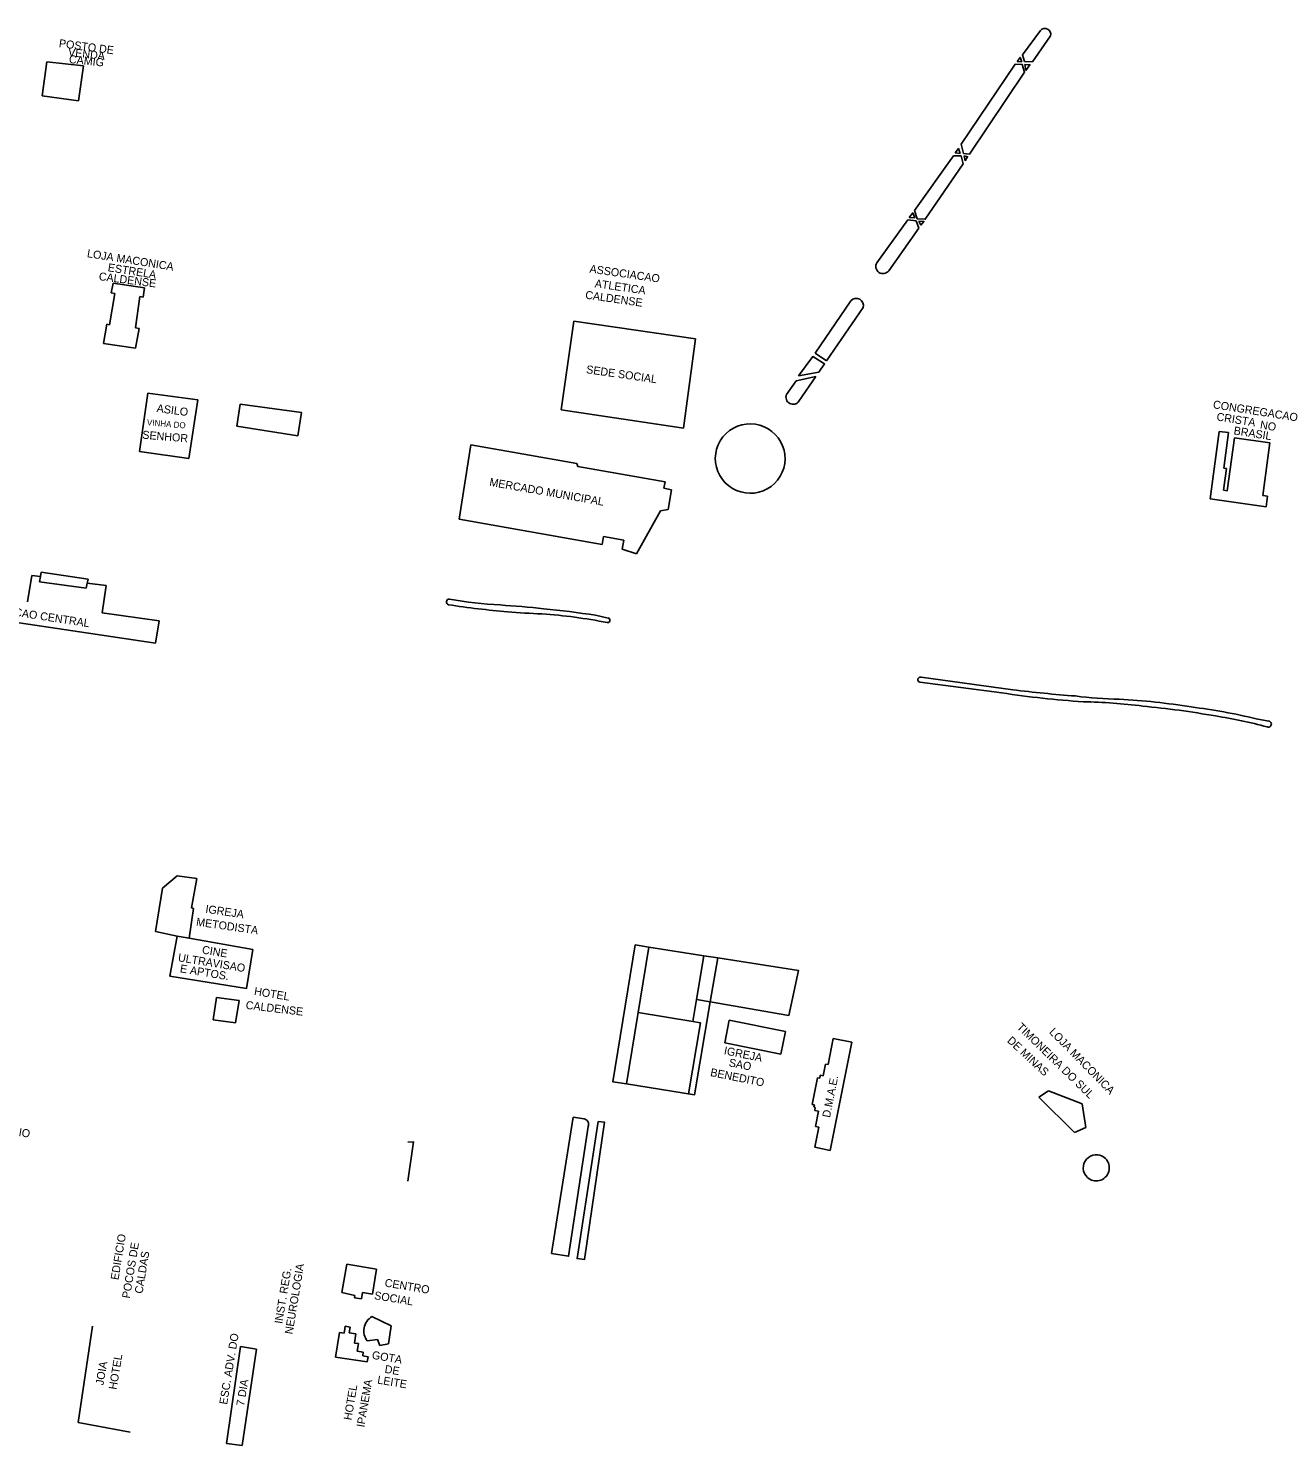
# Model space of a CAD drawing. Extents: x 325899 to 364828, y 7568995 to 7592502.
# Drawn here: x 338292 to 338919, y 7589683 to 7590392 of the extents above; entities that cross this region are included whole.
import ezdxf

# ---------------------------------------------------------------- set-up
doc = ezdxf.new("R2010")
doc.units = 0
for name, color, linetype in [('EDIFEXISTENT', 7, 'Continuous'), ('EDIFIDENTIF', 7, 'Continuous'), ('EDIFOBRAEXIS', 7, 'Continuous')]:
    doc.layers.add(name, color=color, linetype=linetype)

msp = doc.modelspace()

# ---------------------------------------------------------------- linework, layer by layer
at = {"layer": 'EDIFEXISTENT'}
for p, q in [((338298.5, 7590358.22), (338300.86, 7590375.16)), ((338300.86, 7590375.16), (338319.27, 7590373.14)), ((338319.27, 7590373.14), (338316.77, 7590355.73)), ((338316.77, 7590355.73), (338298.5, 7590358.22)), ((338333.09, 7590259.7), (338333.99, 7590264.52)), ((338333.99, 7590264.52), (338349.65, 7590262.24)), ((338349.65, 7590262.24), (338349.07, 7590257.5)), ((338332.26, 7590243.81), (338334.95, 7590259.44)), ((338334.95, 7590259.44), (338333.09, 7590259.7)), ((338347.38, 7590257.88), (338345.28, 7590242.25)), ((338349.07, 7590257.5), (338347.38, 7590257.88)), ((338329.2, 7590234.33), (338330.82, 7590244.15)), ((338330.82, 7590244.15), (338332.26, 7590243.81)), ((338346.98, 7590241.97), (338345.23, 7590232.11)), ((338345.28, 7590242.25), (338346.98, 7590241.97)), ((338557.98, 7590201.17), (338564.38, 7590245.58)), ((338564.38, 7590245.58), (338625.17, 7590236.81)), ((338345.23, 7590232.11), (338329.2, 7590234.33)), ((338625.17, 7590236.81), (338619.17, 7590192.03)), ((338347.19, 7590180.47), (338351.38, 7590209.6)), ((338351.38, 7590209.6), (338376.42, 7590206.23)), ((338376.42, 7590206.23), (338371.94, 7590176.85)), ((338395.96, 7590193.09), (338397.59, 7590204.04)), ((338397.59, 7590204.04), (338428.15, 7590199.96)), ((338428.15, 7590199.96), (338426.38, 7590188.32)), ((338619.17, 7590192.03), (338557.98, 7590201.17)), ((338426.38, 7590188.32), (338395.96, 7590193.09)), ((338882.38, 7590156.68), (338886.99, 7590190.47)), ((338886.99, 7590190.47), (338891.68, 7590189.83)), ((338506.95, 7590146.54), (338512.85, 7590183.7)), ((338512.85, 7590183.7), (338565.82, 7590174.42)), ((338891.68, 7590189.83), (338889.24, 7590172.02)), ((338890.98, 7590160.76), (338894.59, 7590187.17)), ((338894.59, 7590187.17), (338912.31, 7590184.75)), ((338912.31, 7590184.75), (338908.71, 7590158.43)), ((338371.94, 7590176.85), (338347.19, 7590180.47)), ((338565.82, 7590174.42), (338566.37, 7590172.87)), ((338566.37, 7590172.87), (338609.93, 7590165.24)), ((338890.58, 7590171.83), (338889.1, 7590161.02)), ((338889.24, 7590172.02), (338890.58, 7590171.83)), ((338609.93, 7590165.24), (338609.37, 7590162)), ((338609.37, 7590162), (338613.17, 7590161.33)), ((338613.17, 7590161.33), (338611.43, 7590151.42)), ((338910.37, 7590152.68), (338882.38, 7590156.68)), ((338889.1, 7590161.02), (338890.98, 7590160.76)), ((338908.71, 7590158.43), (338911.11, 7590158.1)), ((338911.11, 7590158.1), (338910.37, 7590152.68)), ((338607.65, 7590150.73), (338595.63, 7590129.28)), ((338611.43, 7590151.42), (338607.65, 7590150.73)), ((338578.54, 7590133.98), (338506.95, 7590146.54)), ((338579.22, 7590137.88), (338578.54, 7590133.98)), ((338589.32, 7590136.11), (338579.22, 7590137.88)), ((338588.54, 7590131.64), (338589.32, 7590136.11)), ((338595.63, 7590129.28), (338588.54, 7590131.64)), ((338297.66, 7590117.87), (338298.07, 7590120.1)), ((338298.07, 7590120.1), (338321.51, 7590116.63)), ((338291.23, 7590105.19), (338293.47, 7590118.41)), ((338293.47, 7590118.41), (338297.66, 7590117.87)), ((338297.25, 7590115.25), (338297.66, 7590117.87)), ((338320.61, 7590112.14), (338297.25, 7590115.25)), ((338321.07, 7590114.53), (338320.61, 7590112.14)), ((338321.51, 7590116.63), (338321.07, 7590114.53)), ((338321.07, 7590114.53), (338330.53, 7590113.44)), ((338330.53, 7590113.44), (338328.62, 7590099.84)), ((338355.28, 7590084.54), (338257.69, 7590099.12)), ((338328.62, 7590099.84), (338357.01, 7590095.68)), ((338357.01, 7590095.68), (338355.28, 7590084.54)), ((338358.73, 7589962.07), (338365.98, 7589968.25)), ((338365.98, 7589968.25), (338375.86, 7589966.89)), ((338373.14, 7589952.2), (338375.86, 7589966.89)), ((338355.17, 7589940.37), (338358.73, 7589962.07)), ((338372.06, 7589937.09), (338374.26, 7589951.89)), ((338374.26, 7589951.89), (338373.14, 7589952.2)), ((338355.17, 7589940.37), (338366.09, 7589938.09)), ((338362.43, 7589918.04), (338366.09, 7589938.09)), ((338366.09, 7589938.09), (338372.06, 7589937.09)), ((338372.06, 7589937.09), (338403.95, 7589931.47)), ((338403.95, 7589931.47), (338400.78, 7589911.98)), ((338400.78, 7589911.98), (338362.43, 7589918.04)), ((338384.11, 7589896.36), (338385.65, 7589907.38)), ((338385.65, 7589907.38), (338397.05, 7589905.99)), ((338397.05, 7589905.99), (338395.3, 7589894.77)), ((338395.3, 7589894.77), (338384.11, 7589896.36)), ((338639.76, 7589884.83), (338642.03, 7589896.12)), ((338642.03, 7589896.12), (338670.08, 7589890.5)), ((338670.08, 7589890.5), (338667.8, 7589879.14)), ((338691.42, 7589873.88), (338694.03, 7589886.93)), ((338694.03, 7589886.93), (338703.37, 7589885.05)), ((338667.8, 7589879.14), (338639.76, 7589884.83)), ((338703.37, 7589885.05), (338692.53, 7589830.92)), ((338688.95, 7589868.34), (338690.11, 7589874.15)), ((338690.11, 7589874.15), (338691.42, 7589873.88)), ((338683.57, 7589854.04), (338686.23, 7589867.35)), ((338686.23, 7589867.35), (338687.26, 7589867.15)), ((338687.26, 7589867.15), (338687.55, 7589868.62)), ((338687.55, 7589868.62), (338688.95, 7589868.34)), ((338796.78, 7589857.6), (338801.64, 7589860.75)), ((338814.56, 7589839.91), (338796.78, 7589857.6)), ((338801.64, 7589860.75), (338818.38, 7589854.28)), ((338684.59, 7589853.84), (338683.57, 7589854.04)), ((338684.35, 7589852.64), (338684.59, 7589853.84)), ((338685.06, 7589852.5), (338684.35, 7589852.64)), ((338684.76, 7589851.02), (338685.06, 7589852.5)), ((338686.68, 7589850.64), (338684.76, 7589851.02)), ((338685.15, 7589843), (338686.68, 7589850.64)), ((338818.38, 7589854.28), (338820.24, 7589842.45)), ((338686.74, 7589842.68), (338685.15, 7589843)), ((338684.75, 7589832.71), (338686.74, 7589842.68)), ((338820.24, 7589842.45), (338814.56, 7589839.91)), ((338692.53, 7589830.92), (338684.75, 7589832.71)), ((338448.43, 7589759.9), (338450.8, 7589774.11)), ((338450.8, 7589774.11), (338465.71, 7589771.65)), ((338465.71, 7589771.65), (338463.62, 7589759.14)), ((338454.92, 7589758.53), (338448.43, 7589759.9)), ((338454.73, 7589757.35), (338454.92, 7589758.53)), ((338458.72, 7589759.95), (338458.19, 7589756.77)), ((338463.62, 7589759.14), (338458.72, 7589759.95)), ((338458.19, 7589756.77), (338454.73, 7589757.35)), ((338463.45, 7589747.92), (338473.02, 7589743.23)), ((338323.68, 7589743.11), (338316.65, 7589695.04)), ((338445.21, 7589727.73), (338447.24, 7589739.97)), ((338447.24, 7589739.97), (338449.53, 7589739.59)), ((338449.53, 7589739.59), (338450.12, 7589743.11)), ((338450.12, 7589743.11), (338452.5, 7589742.71)), ((338452.5, 7589742.71), (338452.02, 7589739.86)), ((338452.02, 7589739.86), (338455.45, 7589739.28)), ((338455.45, 7589739.28), (338454.69, 7589734.73)), ((338473.02, 7589743.23), (338471.76, 7589734.27)), ((338390.66, 7589684.56), (338397.65, 7589733.03)), ((338397.65, 7589733.03), (338405.67, 7589731.58)), ((338405.67, 7589731.58), (338398.62, 7589683.41)), ((338454.69, 7589734.73), (338456.63, 7589734.4)), ((338456.63, 7589734.4), (338456, 7589730.59)), ((338456, 7589730.59), (338459.11, 7589730.07)), ((338459.11, 7589730.07), (338458.81, 7589728.31)), ((338466.26, 7589736.44), (338461.1, 7589735.74)), ((338467.36, 7589733.47), (338466.26, 7589736.44)), ((338471.76, 7589734.27), (338467.36, 7589733.47)), ((338461.12, 7589725.27), (338445.21, 7589727.73)), ((338458.81, 7589728.31), (338461.55, 7589727.85)), ((338461.55, 7589727.85), (338461.12, 7589725.27)), ((338316.65, 7589695.04), (338342.59, 7589690.19)), ((338398.62, 7589683.41), (338390.66, 7589684.56))]:
    msp.add_line(p, q, dxfattribs=at)
msp.add_arc((338467.66, 7589740.79), 8.28, 120.57494, 217.60762, dxfattribs=at)
at = {"layer": 'EDIFOBRAEXIS'}
for points in [[(338789.57, 7590375.37), (338788.57, 7590378.79), (338797.59, 7590390.91)], [(338802.68, 7590388.24), (338793.66, 7590375.18)], [(338785.97, 7590375.38), (338787.43, 7590377.44), (338788.33, 7590375.23)], [(338788.33, 7590375.23), (338785.97, 7590375.38)], [(338793.66, 7590375.18), (338789.57, 7590375.37)], [(338759.12, 7590329.44), (338758.03, 7590334.08), (338784.96, 7590374.03), (338788.46, 7590373.96), (338789.67, 7590369.98), (338762.12, 7590329.02)], [(338789.78, 7590373.87), (338792.3, 7590373.78), (338790.33, 7590370.87)], [(338790.33, 7590370.87), (338789.78, 7590373.87)], [(338754.95, 7590329.73), (338756.62, 7590331.87), (338757.47, 7590329.43)], [(338734.67, 7590300.91), (338754.17, 7590328.28), (338757.93, 7590328.19), (338758.91, 7590324.23), (338740.02, 7590296.48), (338736.05, 7590296.69)], [(338757.47, 7590329.43), (338754.95, 7590329.73)], [(338762.12, 7590329.02), (338759.12, 7590329.44)], [(338759.45, 7590328.27), (338761.16, 7590327.8), (338759.97, 7590325.76)], [(338759.97, 7590325.76), (338759.45, 7590328.27)], [(338731.99, 7590297.47), (338733.81, 7590299.68), (338734.83, 7590297.17)], [(338734.83, 7590297.17), (338731.99, 7590297.47)], [(338736.05, 7590296.69), (338734.67, 7590300.91)], [(338715.77, 7590274.78), (338731.36, 7590296.17), (338735.42, 7590295.75)], [(338736.73, 7590292.13), (338721.75, 7590270.74)], [(338735.42, 7590295.75), (338736.73, 7590292.13)], [(338736.74, 7590295.61), (338739.33, 7590295.46), (338737.77, 7590293.6)], [(338737.77, 7590293.6), (338736.74, 7590295.61)], [(338685.03, 7590229.64), (338702.81, 7590255.74)], [(338708.92, 7590252.36), (338690.61, 7590225.75)], [(338676.74, 7590218.16), (338683.74, 7590227.88), (338689.7, 7590224.2), (338686.84, 7590220.15)], [(338690.61, 7590225.75), (338685.03, 7590229.64)], [(338686.84, 7590220.15), (338676.74, 7590218.16)], [(338670.66, 7590208.97), (338675.43, 7590215.69)], [(338675.43, 7590215.69), (338685.28, 7590217.91)], [(338685.28, 7590217.91), (338676.89, 7590205.56)], [(338575.16, 7590098.52), (338581.49, 7590097.17)], [(338778.34, 7590059.75), (338737.3, 7590065.1)], [(338737.95, 7590067.63), (338783.76, 7590061.32)], [(338905.5, 7590046.77), (338911.72, 7590045.68)], [(338595.05, 7589933.71), (338601.76, 7589932.58), (338590.63, 7589864.25), (338583.85, 7589865.24), (338595.05, 7589933.71)], [(338629.36, 7589928.3), (338601.76, 7589932.58)], [(338625.7, 7589906.53), (338629.36, 7589928.3), (338636.26, 7589927.32)], [(338632.55, 7589905.28), (338636.26, 7589927.32), (338676.66, 7589920.95), (338671.85, 7589898.5), (338632.55, 7589905.28), (338624.74, 7589858.83), (338590.63, 7589864.25)], [(338623.84, 7589895.45), (338596.59, 7589900.03)], [(338621.68, 7589859.31), (338627.65, 7589894.8), (338623.84, 7589895.45), (338625.7, 7589906.53), (338632.55, 7589905.28)], [(338553.2, 7589779.46), (338563.95, 7589847.61)], [(338571.58, 7589842.92), (338561.71, 7589778.11), (338553.2, 7589779.46)], [(338563.95, 7589847.61), (338569.45, 7589846.88)], [(338576.43, 7589845.49), (338579.7, 7589845.06), (338569.6, 7589776.44), (338565.96, 7589776.96), (338576.43, 7589845.49)], [(338481.39, 7589835.2), (338484.25, 7589835.24), (338481.39, 7589815.66)]]:
    msp.add_lwpolyline(points, dxfattribs=at)
for centre, radius, start, end in [((338799.84, 7590389.01), 2.94, 344.75865, 139.82121), ((338718.9, 7590272.97), 3.62, 150.02891, 321.90005), ((338705.54, 7590253.45), 3.56, 342.0021, 140.07278), ((338673.96, 7590207.59), 3.57, 157.36807, 325.34764), ((338652.42, 7590176.9), 17.34, 81.03027, 262.29373), ((338652.62, 7590176.87), 17.33, 261.61143, 81.71257), ((338502.09, 7590105.2), 1.41, 82.73871, 255.90677), ((338536.03, 7590288.19), 184.7, 259.46682, 267.3448), ((338558.54, 7590456.8), 357.51, 260.8588, 265.62522), ((338493.06, 7589576.87), 527.93, 83.89682, 86.26165), ((338560.39, 7590427.5), 328.47, 264.91355, 267.90895), ((338529.07, 7589829.58), 270.37, 78.92135, 85.897), ((338508.79, 7589679.77), 423.98, 80.99312, 84.53246), ((338581.26, 7590096.04), 1.16, 257.96055, 78.59972), ((338737.65, 7590066.36), 1.31, 76.81769, 254.33032), ((338849.14, 7590518), 463.69, 261.21726, 266.27847), ((338859.63, 7590662.89), 606.34, 262.81188, 265.78527), ((338839.3, 7590237.63), 181.07, 262.309, 269.27324), ((338820.79, 7589738.93), 318.06, 80.55932, 87.07774), ((338815.35, 7589800.39), 254.92, 82.47678, 89.16897), ((338808.16, 7589616.79), 438.21, 79.88238, 84.68861), ((338840.36, 7589780.83), 273.8, 76.23811, 83.16233), ((338847.41, 7589805.65), 245.45, 74.99704, 81.15888), ((338911.51, 7590044.16), 1.53, 248.77246, 81.93864), ((338568.75, 7589843.95), 3.01, 340.12392, 76.63848), ((338825.54, 7589822.3), 6.56, 82.72397, 260.30239), ((338825.47, 7589822.31), 6.56, 260.88928, 82.13708)]:
    msp.add_arc(centre, radius, start, end, dxfattribs=at)

# ---------------------------------------------------------------- texts
at = {"layer": 'EDIFIDENTIF'}
for s, height, rotation, p in [('POSTO DE', 4, 352.46199, (338306.76, 7590382.61)), ('VENDA', 4, 353.83442, (338311.4, 7590378.14)), ('CAMIG', 4, 354.12057, (338311.81, 7590374.63)), ('LOJA MACONICA', 4, 351.07233, (338320.8, 7590277.6)), ('CALDENSE', 4, 352.59896, (338326.71, 7590266.11)), ('ESTRELA', 4, 350.99941, (338331.18, 7590270.58)), ('ASSOCIACAO', 4, 351.80192, (338572.02, 7590269.89)), ('ATLETICA', 4, 351.80192, (338574.64, 7590262.56)), ('CALDENSE', 4, 351.80192, (338569.86, 7590256.88)), ('SEDE SOCIAL', 4, 351.80192, (338570.33, 7590219.6)), ('CONGREGACAO', 4, 351.02926, (338883.66, 7590202.09)), ('ASILO', 4, 352.44737, (338355.63, 7590200.17)), ('CRISTA', 4, 351.02926, (338885.41, 7590195.96)), ('SENHOR', 4, 355.2297, (338348.51, 7590186.87)), ('VINHA DO', 3, 355.21806, (338350.85, 7590193.54)), ('BRASIL', 4, 351.02926, (338893.99, 7590189.05)), ('NO', 4, 351.02926, (338907.17, 7590191.9)), ('MERCADO MUNICIPAL', 4, 350.05371, (338521.93, 7590163.3)), ('ESTACAO CENTRAL', 4, 351.32484, (338270.59, 7590100.39)), ('IGREJA', 4, 351.57819, (338380, 7589949.88)), ('METODISTA', 4, 351.87823, (338375.37, 7589943.41)), ('ULTRAVISAO', 4, 350.63007, (338366.27, 7589925.63)), ('CINE', 4, 350.63007, (338378.28, 7589929.48)), ('E APTOS.', 4, 350.63007, (338367.24, 7589920.09)), ('HOTEL', 4, 350.63007, (338404.32, 7589908.78)), ('CALDENSE', 4, 353.10459, (338400.16, 7589901.81)), ('TIMONEIRA DO SUL', 4, 315.72236, (338785.51, 7589892.3)), ('LOJA MACONICA', 4, 314.46602, (338801.7, 7589889.91)), ('DE MINAS', 4, 317.03276, (338780.62, 7589885.5)), ('IGREJA', 4, 348.66998, (338639.14, 7589879.1)), ('BENEDITO', 4, 348.66998, (338632.33, 7589868.26)), ('SAO', 4, 348.66998, (338641.57, 7589873.11)), ('D.M.A.E.', 4, 78.66998, (338692.37, 7589847.14)), ('CORREIO', 4, 350.63007, (338267.57, 7589841.4)), ('EDIFICIO', 4, 80.63007, (338336.69, 7589766.02)), ('POCOS DE', 4, 80.63007, (338342.4, 7589756.82)), ('CALDAS', 4, 80.63007, (338348.7, 7589759.17)), ('NEUROLOGIA', 4, 80.63007, (338423.73, 7589738.89)), ('INST. REG.', 4, 80.63007, (338418.62, 7589744.11)), ('CENTRO', 4, 350.55336, (338469.58, 7589763.02)), ('SOCIAL', 4, 350.55336, (338464.34, 7589756.69)), ('ESC. ADV. DO', 4, 80.63007, (338391, 7589703.76)), ('GOTA', 4, 350.55336, (338463.19, 7589726.88)), ('JOIA', 4, 80.63007, (338329.19, 7589713.45)), ('HOTEL', 4, 80.63007, (338335.77, 7589711.22)), ('DE', 4, 350.55336, (338469.57, 7589719.85)), ('7 DIA', 4, 80.63007, (338399.52, 7589703.04)), ('IPANEMA', 4, 80.55336, (338459.65, 7589692.38)), ('LEITE', 4, 350.55336, (338465.91, 7589714.49)), ('HOTEL', 4, 80.55336, (338453.19, 7589695.93))]:
    msp.add_text(s, height=height, rotation=rotation, dxfattribs=at).set_placement(p)

doc.saveas('drawing.dxf')
